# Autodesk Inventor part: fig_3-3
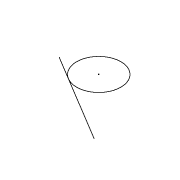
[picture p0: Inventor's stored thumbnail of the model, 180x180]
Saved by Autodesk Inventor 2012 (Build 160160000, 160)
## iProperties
Created: 2009-11
Part Number: fig_3-3
Document SubType Name: Modeling
Designer: Sham
Density: 1 g/cm^3
Material: Default
Author: Sham
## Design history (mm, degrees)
sketch "Sketch1"
  geometry: L1 (-21, -10.296)-(20, -35); C1 r 10.296 at (-4.831, -8.018)
  constraints: 2 end point, 1 centre point, 1 tangent, 1 other
